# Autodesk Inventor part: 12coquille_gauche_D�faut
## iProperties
Created: 2011-01
Part Number: 12coquille_gauche_D�faut
Document SubType Name: Modeling
Designer: eric
Density: 1 g/cm^3
Mass: 230.232 g
Surface Area: 1193.24 cm^2
Volume: 230.232 cm^3
Author: eric
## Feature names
1. Base1
